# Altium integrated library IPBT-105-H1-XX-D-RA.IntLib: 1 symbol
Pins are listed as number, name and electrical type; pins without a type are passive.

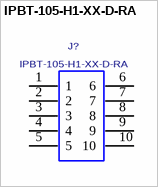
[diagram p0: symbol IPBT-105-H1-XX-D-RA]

## IPBT-105-H1-XX-D-RA
designator J?
0.165 INCH DOUBLE ROW TERMINAL ASSEMBLY; MANUFACTURER: SAMTEC
footprint IPBT-105-H1-XX-D-RA
pins: 1, 2, 3, 4, 5, 6, 7, 8, 9, 10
